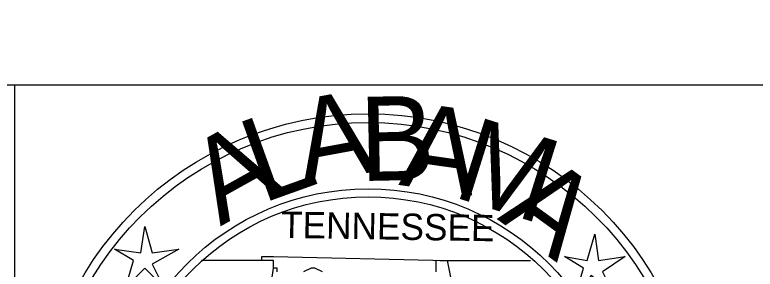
# Model space of a CAD drawing. Extents: x 2193008 to 2198143, y 1236112 to 1237864.
# Drawn here: x 2195038.49 to 2195048.78, y 1237130.48 to 1237134.02 of the extents above; entities that cross this region are included whole.
import ezdxf

# ---------------------------------------------------------------- set-up
doc = ezdxf.new("R2010")
doc.units = 0
for name, color, linetype in [('great seal', 7, 'Continuous'), ('SHT-BDR', 7, 'Continuous'), ('SHT-BNDRY', 7, 'Continuous')]:
    doc.layers.add(name, color=color, linetype=linetype)

msp = doc.modelspace()

# ---------------------------------------------------------------- linework, layer by layer
at = {"layer": 'great seal'}
for p, q in [((2195042.08, 1237130.604), (2195041.081, 1237130.604)), ((2195042.08, 1237130.604), (2195041.081, 1237130.604)), ((2195042.08, 1237130.604), (2195041.081, 1237130.604)), ((2195044.392, 1237130.604), (2195045.653, 1237130.604)), ((2195044.392, 1237130.604), (2195045.653, 1237130.604)), ((2195044.392, 1237130.604), (2195045.653, 1237130.604))]:
    msp.add_line(p, q, dxfattribs=at)
for points in [[(2195040.293, 1237131.077), (2195040.398, 1237130.71), (2195040.766, 1237130.762), (2195040.398, 1237130.552), (2195040.556, 1237130.237), (2195040.293, 1237130.499), (2195040.03, 1237130.237), (2195040.135, 1237130.604), (2195039.873, 1237130.762), (2195040.24, 1237130.71)], [(2195040.293, 1237131.077), (2195040.398, 1237130.71), (2195040.766, 1237130.762), (2195040.398, 1237130.552), (2195040.556, 1237130.237), (2195040.293, 1237130.499), (2195040.03, 1237130.237), (2195040.135, 1237130.604), (2195039.873, 1237130.762), (2195040.24, 1237130.71)], [(2195040.293, 1237131.077), (2195040.398, 1237130.71), (2195040.766, 1237130.762), (2195040.398, 1237130.552), (2195040.556, 1237130.237), (2195040.293, 1237130.499), (2195040.03, 1237130.237), (2195040.135, 1237130.604), (2195039.873, 1237130.762), (2195040.24, 1237130.71)], [(2195046.547, 1237130.972), (2195046.599, 1237130.604), (2195046.967, 1237130.657), (2195046.652, 1237130.447), (2195046.809, 1237130.131), (2195046.494, 1237130.394), (2195046.284, 1237130.131), (2195046.389, 1237130.499), (2195046.126, 1237130.657), (2195046.442, 1237130.604)], [(2195046.547, 1237130.972), (2195046.599, 1237130.604), (2195046.967, 1237130.657), (2195046.652, 1237130.447), (2195046.809, 1237130.131), (2195046.494, 1237130.394), (2195046.284, 1237130.131), (2195046.389, 1237130.499), (2195046.126, 1237130.657), (2195046.442, 1237130.604)], [(2195046.547, 1237130.972), (2195046.599, 1237130.604), (2195046.967, 1237130.657), (2195046.652, 1237130.447), (2195046.809, 1237130.131), (2195046.494, 1237130.394), (2195046.284, 1237130.131), (2195046.389, 1237130.499), (2195046.126, 1237130.657), (2195046.442, 1237130.604)]]:
    msp.add_lwpolyline(points, close=True, dxfattribs=at)
for points in [[(2195041.607, 1237127.241), (2195042.08, 1237130.499), (2195042.08, 1237130.604), (2195042.08, 1237130.604), (2195042.08, 1237130.604), (2195041.922, 1237130.604), (2195041.922, 1237130.657), (2195042.08, 1237130.657), (2195044.497, 1237130.604), (2195044.97, 1237128.24)], [(2195041.607, 1237127.241), (2195042.08, 1237130.499), (2195042.08, 1237130.604), (2195042.08, 1237130.604), (2195042.08, 1237130.604), (2195041.922, 1237130.604), (2195041.922, 1237130.657), (2195042.08, 1237130.657), (2195044.497, 1237130.604), (2195044.97, 1237128.24)], [(2195041.607, 1237127.241), (2195042.08, 1237130.499), (2195042.08, 1237130.604), (2195042.08, 1237130.604), (2195042.08, 1237130.604), (2195041.922, 1237130.604), (2195041.922, 1237130.657), (2195042.08, 1237130.657), (2195044.497, 1237130.604), (2195044.97, 1237128.24)], [(2195042.132, 1237130.447), (2195042.132, 1237130.499), (2195042.08, 1237130.499), (2195042.08, 1237130.604), (2195042.08, 1237130.604), (2195042.08, 1237130.604)], [(2195042.132, 1237130.447), (2195042.132, 1237130.499), (2195042.08, 1237130.499), (2195042.08, 1237130.604), (2195042.08, 1237130.604), (2195042.08, 1237130.604)], [(2195042.132, 1237130.447), (2195042.132, 1237130.499), (2195042.08, 1237130.499), (2195042.08, 1237130.604), (2195042.08, 1237130.604), (2195042.08, 1237130.604)], [(2195044.34, 1237130.604), (2195044.34, 1237130.604), (2195044.34, 1237130.604), (2195044.34, 1237130.499), (2195044.34, 1237130.447)], [(2195044.34, 1237130.604), (2195044.34, 1237130.604), (2195044.34, 1237130.604), (2195044.34, 1237130.499), (2195044.34, 1237130.447)], [(2195044.34, 1237130.604), (2195044.34, 1237130.604), (2195044.34, 1237130.604), (2195044.34, 1237130.499), (2195044.34, 1237130.447)], [(2195042.763, 1237130.447), (2195042.658, 1237130.499), (2195042.605, 1237130.499), (2195042.5, 1237130.447)], [(2195042.763, 1237130.447), (2195042.658, 1237130.499), (2195042.605, 1237130.499), (2195042.5, 1237130.447)], [(2195042.763, 1237130.447), (2195042.658, 1237130.499), (2195042.605, 1237130.499), (2195042.5, 1237130.447)]]:
    msp.add_lwpolyline(points, dxfattribs=at)
for radius in [4.599, 4.599, 4.599, 4.478, 4.478, 4.478, 3.556, 3.556, 3.556, 3.444, 3.444, 3.444]:
    msp.add_circle((2195043.397, 1237128.045), radius, dxfattribs=at)
at = {"layer": 'SHT-BDR'}
msp.add_lwpolyline([(2194882.86, 1237133.046), (2195182.86, 1237133.046), (2195182.86, 1237323.046), (2194882.86, 1237323.046)], close=True, dxfattribs=at)
at = {"layer": 'SHT-BNDRY'}
msp.add_line((2195038.488, 1237123.036), (2195038.488, 1237133.046), dxfattribs=at)

# ---------------------------------------------------------------- texts
at = {"layer": 'great seal'}
for s, height, rotation, p in [('A', 1.17, 10.4972, (2195042.5, 1237131.656)), ('A', 1.17, 10.4972, (2195042.5, 1237131.656)), ('A', 1.17, 10.4972, (2195042.5, 1237131.656)), ('B', 1.17, 1.1955, (2195043.288, 1237131.708)), ('B', 1.17, 1.1955, (2195043.288, 1237131.708)), ('B', 1.17, 1.1955, (2195043.288, 1237131.708)), ('A', 1.17, 351.8938, (2195043.814, 1237131.656)), ('A', 1.17, 351.8938, (2195043.814, 1237131.656)), ('A', 1.17, 351.8938, (2195043.814, 1237131.656)), ('L', 1.17, 19.7988, (2195041.922, 1237131.393)), ('L', 1.17, 19.7988, (2195041.922, 1237131.393)), ('L', 1.17, 19.7988, (2195041.922, 1237131.393)), ('M', 1.17, 342.5921, (2195044.55, 1237131.498)), ('A', 1.17, 29.1005, (2195041.344, 1237131.077)), ('A', 1.17, 29.1005, (2195041.344, 1237131.077)), ('A', 1.17, 29.1005, (2195041.344, 1237131.077)), ('A', 1.17, 323.9887, (2195045.18, 1237131.183)), ('A', 1.17, 323.9887, (2195045.18, 1237131.183)), ('A', 1.17, 323.9887, (2195045.18, 1237131.183)), ('TENNESSEE', 0.3661, 359.041, (2195042.185, 1237130.92)), ('TENNESSEE', 0.3661, 359.041, (2195042.185, 1237130.92)), ('TENNESSEE', 0.3661, 359.041, (2195042.185, 1237130.92))]:
    msp.add_text(s, height=height, rotation=rotation, dxfattribs=at).set_placement(p)

doc.saveas('drawing.dxf')
